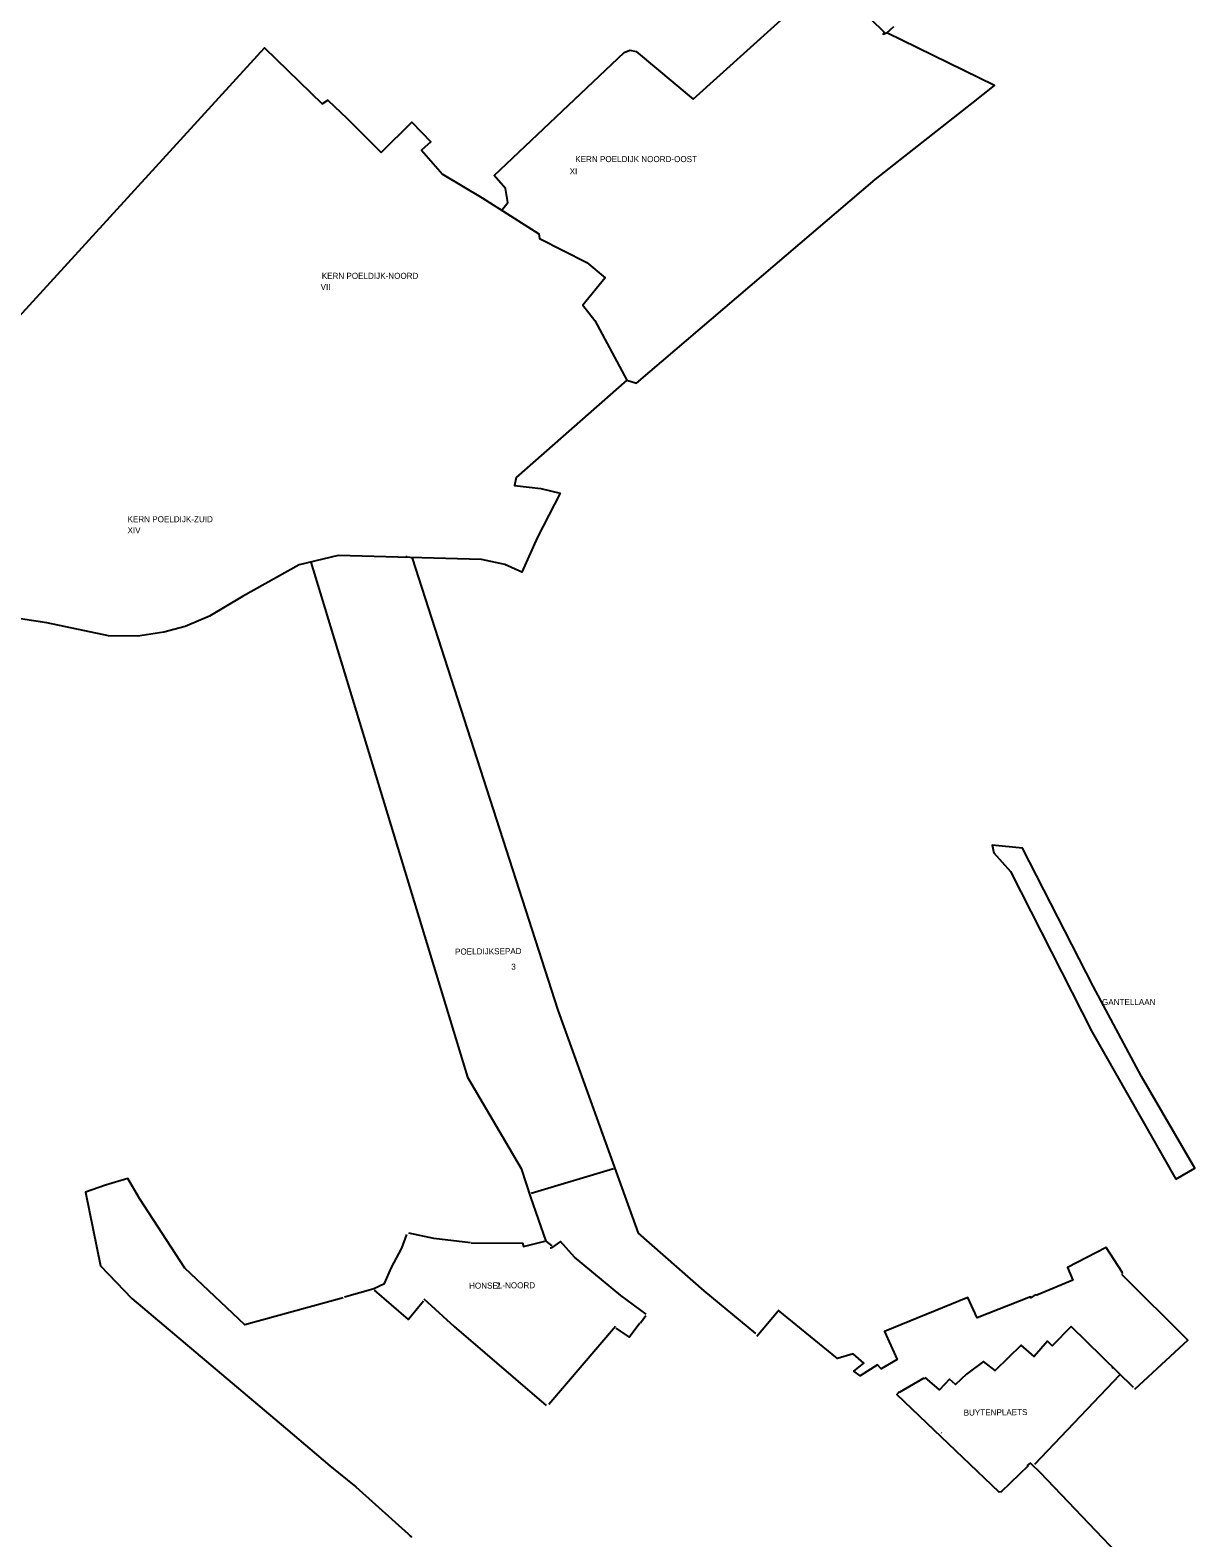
# Model space of a CAD drawing. Extents: x 69068 to 80855, y 440023 to 451362.
# Drawn here: x 74444 to 76178, y 447248 to 449491 of the extents above; entities that cross this region are included whole.
import ezdxf

# ---------------------------------------------------------------- set-up
doc = ezdxf.new("R2010")
doc.units = 0
for name, color, linetype in [('Bemalingsgebiedsgrens', 7, 'Continuous'), ('Bemalingsgebiedsnummer', 7, 'Continuous'), ('RIO_Leidingen', 7, 'Continuous')]:
    doc.layers.add(name, color=color, linetype=linetype)

msp = doc.modelspace()

# ---------------------------------------------------------------- linework, layer by layer
at = {"layer": 'Bemalingsgebiedsgrens'}
for p, q in [((75190.1, 447760.4), (75312.4, 447797)), ((75352.7, 447567.7), (75360.3, 447578.7)), ((75315.6, 447562.3), (75216.3, 447446.2)), ((75773.4, 447484.8), (75778.7, 447485.6)), ((75939.4, 447357.3), (76066, 447490))]:
    msp.add_line(p, q, dxfattribs=at)
for points in [[(75146.2, 449223), (75154.9, 449234.3), (75151.8, 449255.5), (75134.7, 449274.7), (75328.3, 449457.9), (75336.9, 449461.3), (75346.2, 449459.1), (75431.1, 449388.5), (75631.7, 449569.8), (75715.6, 449487.7), (75713.9, 449484.8), (75719.1, 449486.9), (75729.7, 449496.3)], [(75845.8, 449381.7), (75879.3, 449408.4), (75719.1, 449486.9)], [(74322.7, 448950.4), (74793, 449464.6), (74878.7, 449381.1), (74887.2, 449386.8), (74916, 449359.7), (74966.4, 449309), (75012.1, 449353.9), (75040.4, 449324.7), (75026.7, 449312.5), (75057.8, 449276.6), (75117.1, 449241.5), (75201.2, 449187.8), (75202.5, 449181.2), (75272.5, 449145.2), (75300, 449122.6), (75266.7, 449081.8), (75284.6, 449058.8), (75332.2, 448970.1), (75167.4, 448825.1), (75165, 448813.6), (75204.1, 448808.9), (75233.2, 448801.8), (75199.3, 448736.6), (75175.9, 448684.7), (75150.7, 448696), (75115.7, 448703.2), (74902.4, 448709.4), (74844.5, 448695.5), (74760, 448648.2), (74710.9, 448618.8), (74675, 448603.4), (74643, 448595.3), (74604.2, 448589.2), (74560.8, 448589.7), (74469, 448609.2), (74429.9, 448615)], [(75332.2, 448970.1), (75346.5, 448965.9), (75702, 449268.7), (75845.8, 449381.7), (75845.8, 449381.7)], [(75284.7, 449135.1), (75284.9, 449135)], [(75319.2, 448994.4), (75320.5, 448991.9)], [(74861.7, 448699.6), (75095.3, 447933.3), (75174.9, 447797), (75182.5, 447774.4), (75189, 447754.4)], [(75005.4, 448707.5), (75003.2, 448707.5)], [(75524.5, 447551.5), (75447.4, 447615), (75349.5, 447701.1), (75229.9, 448032.6), (75013.3, 448705.2)], [(74909.9, 447605), (74763.9, 447564.5), (74674.2, 447648.8), (74606.7, 447752.5), (74589.4, 447782.3), (74556.5, 447772.2), (74526.7, 447762.1), (74548.7, 447652.4), (74595.7, 447603.8), (74824.4, 447410.9), (74890.4, 447354.8), (74928.8, 447323.7), (75011.6, 447248.9), (75009.6, 447250.4)], [(75189, 447754.4), (75211.9, 447689.3), (75220.6, 447681.9)], [(75099.5, 447686.5), (75044.8, 447693.1), (75007.7, 447700.8)], [(74955.8, 447618.7), (74971.8, 447626.2), (74981.9, 447649.9), (74997.5, 447678.6), (75005, 447699.2)], [(75100.7, 447686.5), (75176.9, 447686), (75178.5, 447680.9), (75210.1, 447689.2)], [(75220.1, 447678.7), (75218.1, 447678.8)], [(75360.8, 447580.5), (75323.4, 447608.4), (75254.2, 447665.4), (75233.6, 447688.4), (75220, 447679)], [(76069.8, 447640.3), (76069.5, 447642.9), (76045.8, 447679.7), (75988.3, 447649.8), (75996.2, 447631.2), (75942.3, 447608.7), (75939.8, 447609), (75933.5, 447605), (75933.2, 447606.2), (75853.9, 447575), (75840, 447605.4), (75715.9, 447554.6), (75734.7, 447513.1), (75710.8, 447498.9), (75705.6, 447504.9), (75679.5, 447488.8), (75669.9, 447495.5), (75684.8, 447507.4), (75669.1, 447521.5), (75645.6, 447514.4), (75557.6, 447586.6)], [(76068.4, 447639.9), (76167.4, 447541.8), (76088.1, 447468.6)], [(74911.9, 447606.4), (74957.6, 447619.2)], [(74956.4, 447616.1), (75006.6, 447572.4), (75029.8, 447600.3)], [(75030.3, 447603.5), (75075.2, 447562.3), (75212.1, 447444.7)], [(75316.1, 447559.4), (75335.5, 447546.4), (75351.8, 447567.8)], [(75526, 447547.9), (75557.6, 447585.6)], [(76086.2, 447471.5), (75993.7, 447562.3), (75965.1, 447533.3), (75958.2, 447540.1), (75938.5, 447517.5), (75919.2, 447534.4), (75880.4, 447496.7), (75863.2, 447510), (75837.7, 447491.4), (75821.3, 447475.9), (75812.5, 447483.9), (75797.5, 447468.1), (75776.2, 447486.1)], [(76054.6, 447500.1), (76054, 447499.5)], [(75738.8, 447464), (75738.2, 447464.6), (75774.9, 447485.7)], [(75889.8, 447316.3), (75886.5, 447315.5), (75778.7, 447418.4), (75734, 447461.1), (75737.9, 447465.5)], [(75801, 447403.4), (75800.6, 447403.8)], [(75929.5, 447354.7), (75889.5, 447316.2)], [(75929.4, 447355.6), (75928.4, 447355.1), (75933.3, 447358.6), (75947.4, 447344.9), (76061.2, 447225.9)]]:
    msp.add_lwpolyline(points, dxfattribs=at)
msp.add_lwpolyline([(76149.6, 447781.3), (76177.7, 447797.6), (76098.3, 447934.3), (76026.2, 448068.3), (75921.3, 448274), (75875.9, 448278.5), (75878.7, 448266.9), (75903.5, 448238.9), (76025, 448000.2)], close=True, dxfattribs=at)

# ---------------------------------------------------------------- texts
at = {"layer": 'Bemalingsgebiedsnummer'}
for s, p in [('XI', (75247.2, 449276.4)), ('VII', (74876.5, 449104.5)), ('XIV', (74589.1, 448742.4)), ('2', (75137.7, 447618.5))]:
    msp.add_text(s, height=9, dxfattribs=at).set_placement(p)
msp.add_text('3', height=9, rotation=0.1635, dxfattribs=at).set_placement((75160.3, 448092.9))
at = {"layer": 'RIO_Leidingen'}
for s, p in [('KERN POELDIJK NOORD-OOST', (75255.5, 449294.6)), ('KERN POELDIJK-NOORD', (74878.2, 449120.9)), ('KERN POELDIJK-ZUID', (74589.1, 448758.8)), ('GANTELLAAN', (76039.5, 448040.4))]:
    msp.add_text(s, height=9, dxfattribs=at).set_placement(p)
for s, rotation, p in [('POELDIJKSEPAD', 0.5, (75076.6, 448115.4)), ('HONSEL-NOORD', 0.422, (75097.5, 447618.3)), ('BUYTENPLAETS', 0.5, (75833.6, 447429.5))]:
    msp.add_text(s, height=9, rotation=rotation, dxfattribs=at).set_placement(p)

doc.saveas('drawing.dxf')
